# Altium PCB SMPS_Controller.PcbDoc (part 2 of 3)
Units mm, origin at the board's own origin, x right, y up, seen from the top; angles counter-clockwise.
Board outline 157 x 106 mm, 2 copper layers (Top Layer, Bottom Layer); 245 components, 175 nets, 948 pads, 171 vias.
Unrouted connection lines stored in the file: 2.
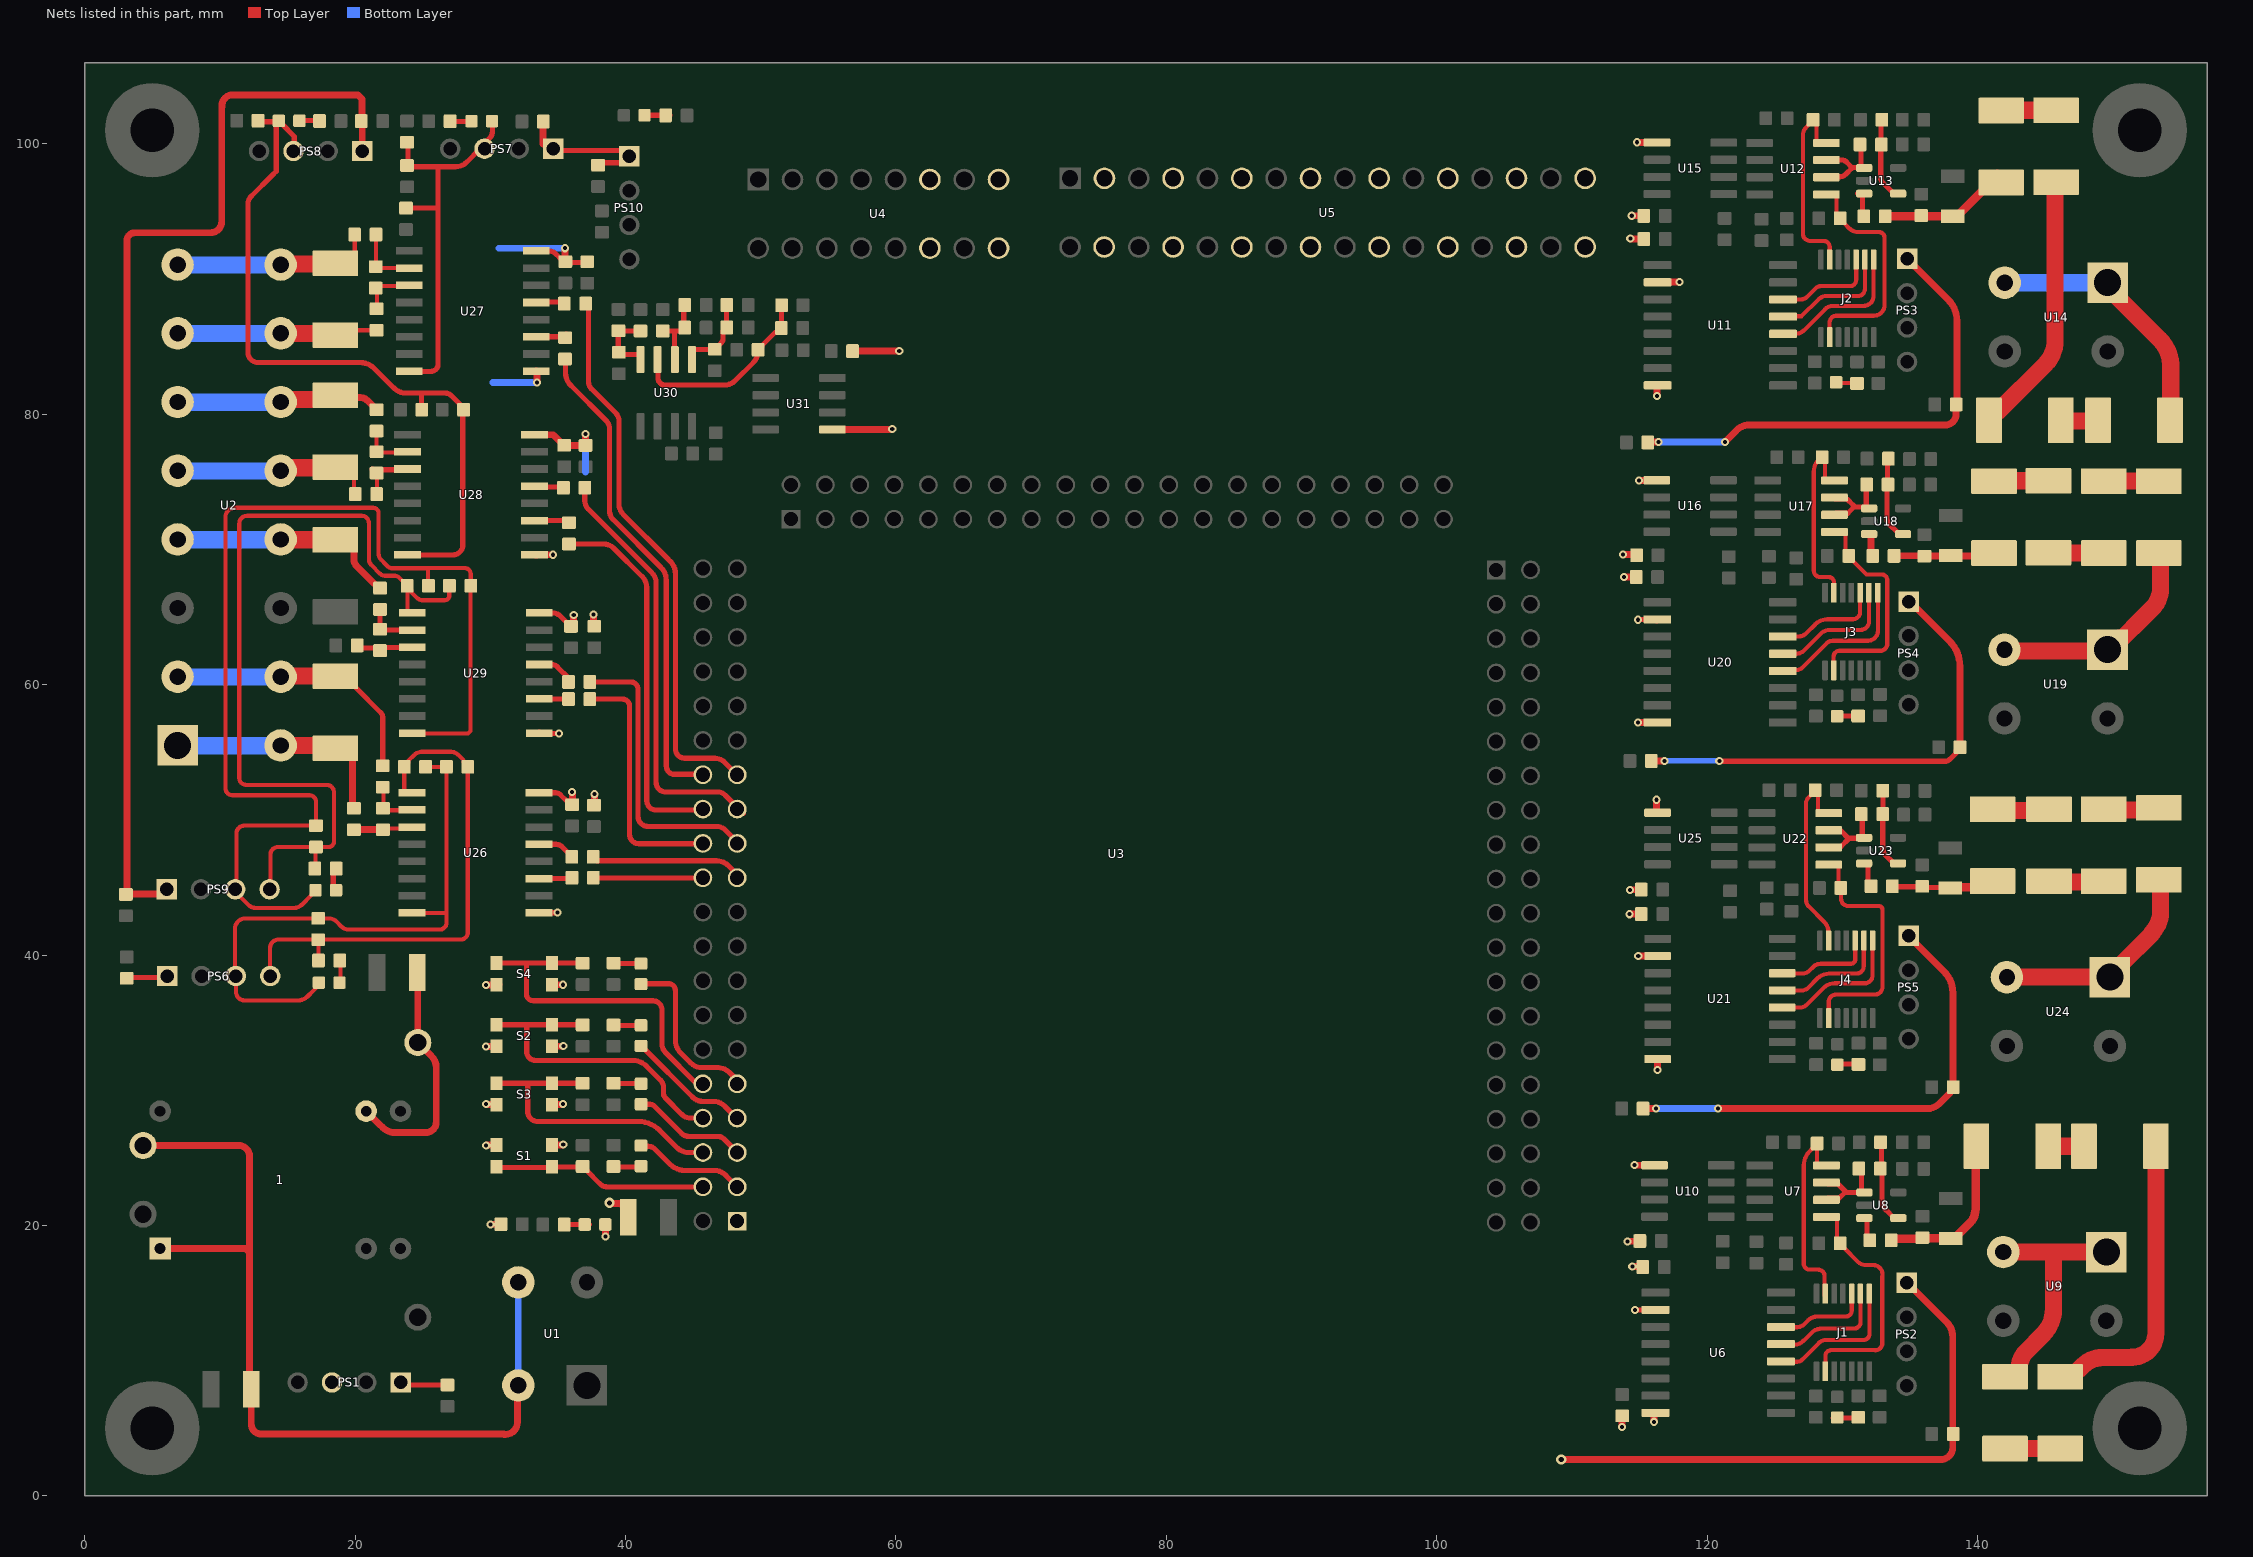
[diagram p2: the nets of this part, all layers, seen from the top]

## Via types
v1: diameter 0.6, hole 0.3, Top Layer to Bottom Layer, tented both sides, 163 vias
v2: diameter 0.762, hole 0.381, Top Layer to Bottom Layer, tented both sides, 8 vias

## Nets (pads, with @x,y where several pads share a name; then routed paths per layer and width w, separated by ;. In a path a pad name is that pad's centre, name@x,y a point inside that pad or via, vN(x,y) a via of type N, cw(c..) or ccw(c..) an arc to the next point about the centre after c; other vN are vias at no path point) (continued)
5V0_ISO3: C82.1 C83.1 C88.2 PS9.4 R69.2 U29.1 | length 62.7
  Top Layer w0.305: 11.43,53.087 ccw(c11.93,53.087) 11.951,52.588 cw(c11.962,52.283) 11.962,52.588 17.877,52.588 cw(c17.877,52.023) 18.441,52.023 ; 11.43,53.089 11.43,71.897 cw(c12.022,71.897) 12.022,72.488 20.488,72.488 cw(c20.488,71.956) 21.02,71.956 21.02,69.286 ccw(c21.629,69.286) 21.198,68.855 ; PS9.4@13.678,44.856 13.735,44.913 13.735,47.417 cw(c14.302,47.417) 14.302,47.984 C88.2@17.098,47.984 ; R69.2@17.062,46.272 C88.2@17.062,47.948 ; C88.2@17.102,47.988 18.034,47.988 ccw(c18.034,48.393) 18.438,48.393 18.438,52.023 ; 21.197,68.854 21.856,68.196 ; 21.857,68.197 ccw(c22.208,68.548) 22.208,68.052 22.947,68.052 cw(c22.947,67.627) 23.247,67.927 ; 23.246,67.926 23.504,67.668 23.772,67.668 C83.1@23.876,67.564 ; C83.1@23.848,67.31 23.848,67.133 23.985,67.133 24.166,66.952 24.166,66.815 24.535,66.446 ccw(c25.06,66.971) 25.06,66.229 ; C83.1@23.876,67.082 23.876,65.532 24.003,65.405 U29.1@24.257,65.405 ; 25.06,66.237 26.622,66.237 ; 26.622,66.24 ccw(c26.622,66.584) 26.965,66.584 C82.1@26.965,67.297
5V0_ISO4: C61.1 C62.1 C67.2 PS6.4 R51.2 U26.1 | length 39.1
  Top Layer w0.305: PS6.4@13.716,38.1 13.716,40.52 cw(c14.338,40.52) 14.338,41.142 C67.2@17.265,41.142 ; R51.2@17.244,39.37 17.3,39.426 C67.2@17.3,40.952 ; C67.2@17.428,40.943 17.628,41.143 27.802,41.143 ccw(c27.802,41.675) 28.334,41.675 C61.1@28.334,53.92 ; U26.1@23.622,52.07 23.632,52.08 C62.1@23.632,53.917 23.949,54.235 23.949,54.374 24.376,54.8 ; 24.374,54.802 cw(c24.925,54.251) 24.925,55.03 27.093,55.03 cw(c27.093,54.314) 27.599,54.82 ; 27.602,54.823 28.017,54.409 28.017,54.278 28.187,54.108 C61.1@28.442,54.108
AGND_ISO1: C68.2 C69.2 C74.1 D11.C PS7.3 U27.8 | length 29.5
  Top Layer w0.381: C69.2@23.553,95.252 26.124,95.252 ; C68.2@23.844,98.396 23.907,98.46 C74.1@23.907,100.156 ; C68.2@23.907,98.304 26.138,98.304 27.434,98.304 27.435,98.304 ccw(c27.435,99.463) 28.255,98.644 PS7.3@29.21,99.598 ; U27.8@24.017,83.171 25.614,83.171 ccw(c25.614,83.695) 26.138,83.695 26.138,95.252 26.138,98.214 ; PS7.3@29.21,99.636 29.21,99.686 29.962,100.437 ccw(c29.499,100.9) 30.153,100.9 30.153,101.409 D11.C@30.128,101.684
AGND_ISO2: C75.2 C76.2 C81.1 D12.C PS8.3 U28.8 | length 55
  Top Layer w0.381: 12.075,84.582 12.075,95.553 cw(c12.893,95.553) 12.315,96.131 ; 12.079,84.582 12.079,84.562 ccw(c12.82,84.562) 12.82,83.82 14.272,83.82 20.377,83.82 cw(c20.377,82.361) 21.41,83.392 21.411,83.39 22.889,81.912 ; 12.325,96.121 13.89,97.686 14.173,97.968 14.173,101.518 D12.C@14.358,101.704 ; C81.1@12.751,101.636 D12.C@14.202,101.636 ; D12.C@14.358,101.686 14.366,101.686 14.622,101.429 14.622,101.421 15.494,100.549 PS8.3@15.494,100.076 ; 22.892,81.916 ccw(c23.747,82.77) 23.747,81.562 24.92,81.562 26.694,81.562 cw(c26.694,80.996) 27.094,81.396 27.743,80.747 27.743,80.656 C75.2@28.022,80.337 ; U28.8@23.876,69.596 27.231,69.596 ccw(c27.231,70.333) 27.968,70.333 C75.2@27.968,80.264 ; C76.2@24.92,80.264 24.92,81.493
AGND_ISO3: C82.2 C83.2 C88.1 D13.C PS9.3 U29.8 | length 86
  Top Layer w0.305: PS9.3@11.138,44.856 11.214,44.932 11.214,48.965 cw(c11.817,48.965) 11.817,49.568 C88.1@17.102,49.568 17.102,51.346 ccw(c16.632,51.346) 16.632,51.816 10.922,51.816 cw(c10.922,52.324) 10.414,52.324 10.414,72.4 cw(c11.093,72.4) 11.093,73.079 21.336,73.079 cw(c21.336,72.677) 21.738,72.677 21.738,69.701 ccw(c22.438,69.701) 21.943,69.206 ; PS9.3@11.143,44.674 12.116,43.702 ; 12.117,43.703 ccw(c12.649,44.235) 12.649,43.483 15.507,43.483 ccw(c15.507,44.183) 16.002,43.688 ; 16.017,43.673 16.773,44.429 16.773,44.489 D13.C@17.075,44.791 ; 21.945,69.208 22.268,68.885 22.402,68.75 ; 22.406,68.754 ccw(c22.766,69.114) 22.766,68.605 25.4,68.605 ; U29.8@24.221,56.409 24.249,56.381 28.353,56.381 28.531,56.56 28.531,67.283 28.554,67.67 28.554,68.173 ccw(c28.109,68.173) 28.109,68.618 25.4,68.618 ; 25.4,68.513 25.4,67.668 C83.2@25.504,67.564
AGND_ISO4: C61.2 C62.2 C67.1 D10.C PS6.3 U26.8 | length 44.2
  Top Layer w0.305: 16.454,36.917 cw(c15.795,37.576) 15.795,36.643 11.819,36.643 cw(c11.819,37.276) 11.186,37.276 11.186,38.09 11.118,38.158 11.118,41.946 cw(c11.874,41.946) 11.874,42.702 C67.1@17.255,42.702 ; 16.459,36.912 16.91,37.363 16.91,37.369 17.207,37.666 D10.C@17.212,37.666 ; C67.1@17.27,42.717 17.288,42.7 18.07,42.7 cw(c18.07,41.917) 18.623,42.47 ; 18.622,42.469 19.011,42.079 ; 19.015,42.083 ccw(c19.501,42.568) 19.501,41.882 26.262,41.882 ccw(c26.262,42.374) 26.754,42.374 26.754,43.112 26.754,53.562 C61.2@26.754,53.92 ; U26.8@24.207,43.112 26.674,43.112 26.728,43.166 ; C62.2@25.212,53.917 26.347,53.917 C61.2@26.702,53.562 ; C61.2@26.347,53.919 C61.2@26.754,53.92
GND_3V3: 1.10 1.500 C1.2 C2.2 C4.1 C5.2 C15.2 C17.1 C19.2 C29.1 C31.2 C33.2 C43.2 C45.1 C47.2 C57.1 C59.2 C63.2 C64.2 C66.1 C70.2 C71.2 C73.1 C77.2 C78.2 C80.1 C84.2 C85.2 C87.1 C95.2 C97.1 C99.1 C100.2 C101.2 C102.2 C103.2 D1.C PS1.1 PS1.3 PS2.1 PS3.1 PS4.1 PS5.1 PS6.1 PS7.1 PS8.1 PS9.1 PS10.1 S1.1 S1.3 S2.1 S2.3 S3.1 S3.3 S4.1 S4.3 U3.A01 U4.6 U4.8 U5.2 U5.4 U5.6 U5.8 U5.10 U5.12 U5.14 U5.16 U6.2 U6.8 U10.5 U11.2 U11.8 U15.5 U16.5 U20.2 U20.8 U21.2 U21.8 U25.5 U26.9 U26.16 U27.9 U27.16 U28.9 U28.16 U29.9 U29.16 U31.5 | length 345.6
  Top Layer w0.381: C66.1@3.107,38.275 3.171,38.339 5.851,38.339 PS6.1@6.072,38.559 ; PS1.1@23.368,8.382 23.561,8.189 26.383,8.189 C1.2@26.416,8.156 ; U28.9@33.274,69.596 33.363,69.507 U28.9@33.458,69.507 ; U27.16@33.401,92.075 34.354,92.075 cw(c34.354,91.435) 34.807,91.887 ; U26.9@33.605,43.112 33.623,43.129 34.945,43.129 v1(34.963,43.147) ; U26.16@33.605,52.002 34.828,52.002 cw(c34.828,51.518) 35.17,51.86 ; U29.16@33.619,65.299 34.601,65.299 cw(c34.601,64.45) 35.201,65.051 ; U29.9@33.64,56.388 33.643,56.39 35.068,56.39 v1(35.087,56.371) ; PS7.1@33.906,99.994 PS7.1@34.263,99.636 ; PS7.1@34.29,99.636 34.408,99.518 39.785,99.518 PS10.1@40.23,99.074 ; 34.811,91.891 35.134,91.568 35.273,91.568 C70.2@35.553,91.288 ; 35.171,51.861 35.63,51.403 35.772,51.403 C63.2@36.051,51.123 ; 35.199,65.049 35.657,64.591 35.657,64.466 35.736,64.386 C84.2@35.862,64.386 ; C70.2@35.754,91.234 C71.2@37.171,91.234 ; C71.2@37.171,91.278 37.263,91.186 C71.2@37.472,91.186 ; C97.1@37.853,98.298 C97.1@37.974,98.419 ; C97.1@38.088,98.436 38.256,98.605 39.666,98.605 39.824,98.763 PS10.1@39.824,99.241 ; v1(114.273,43.018) v1@114.276,43.021 ; v1(114.313,44.815) v1@114.325,44.826 ; v1(114.675,13.73) 114.689,13.743 116.171,13.743 U6.2@116.184,13.757 ; v1(114.901,64.797) 114.915,64.811 116.241,64.811 U20.2@116.274,64.778 ; C59.2@115.127,44.826 C59.2@115.138,44.837 ; C47.2@115.136,43.021 C47.2@115.138,43.023 ; v1@120.93,54.33 137.598,54.33 ccw(c137.598,54.85) 137.966,54.482 138.43,54.946 C45.1@138.43,55.118
  Top Layer w0.508: C87.1@3.046,44.482 3.122,44.558 3.122,92.839 cw(c3.702,92.839) 3.702,93.419 9.306,93.419 ccw(c9.306,94.251) 10.138,94.251 10.138,102.732 ; C87.1@3.097,44.506 5.892,44.506 PS9.1@6.063,44.678 ; 10.148,102.732 10.148,102.83 cw(c10.927,102.83) 10.927,103.609 20.206,103.609 20.503,103.311 20.503,101.729 C80.1@20.458,101.684 20.533,101.608 PS8.1@20.533,99.481 ; 1.10@20.818,28.448 21.839,27.427 ; 21.844,27.432 22.016,27.26 ; 22.016,27.26 ccw(c22.953,28.197) 22.953,26.872 23.196,26.872 25.235,26.872 ccw(c25.235,27.636) 25.999,27.636 25.999,31.68 ccw(c24.822,31.68) 25.654,32.512 1.500@24.638,33.528 C4.1@24.638,39.37 ; v1(29.669,37.782) 29.682,37.795 30.627,37.795 S4.1@30.651,37.819 ; v1(29.671,33.243) 29.674,33.24 30.458,33.24 S2.1@30.462,33.236 ; v1(29.697,28.965) 29.714,28.947 30.433,28.947 S3.1@30.462,28.918 ; v1(29.697,25.922) 29.709,25.934 S1.3@30.48,25.934 ; v1(30.006,20.074) 30.014,20.083 30.781,20.083 C2.2@30.789,20.091 ; U28.16@33.274,78.486 33.283,78.477 34.659,78.477 35.208,77.927 35.208,77.92 35.424,77.704 C77.2@35.432,77.704 ; U27.9@33.401,83.185 33.422,83.185 33.448,83.16 v1(33.448,82.344) ; U28.9@33.553,69.602 34.64,69.602 v1(34.646,69.607) ; U29.9@33.619,56.409 U29.9@33.64,56.388 ; PS7.1@33.906,99.994 C73.1@33.906,101.865 ; S1.1@34.562,25.946 34.574,25.958 35.385,25.958 v1(35.397,25.97) ; S3.3@34.562,28.918 34.598,28.954 35.369,28.954 v1(35.387,28.972) ; S2.3@34.562,33.236 34.579,33.253 35.382,33.253 v1(35.398,33.269) ; S4.3@34.562,37.808 34.567,37.803 35.377,37.803 v1(35.381,37.799) ; C77.2@35.507,77.661 C77.2@35.464,77.704 35.47,77.698 36.804,77.698 C78.2@36.83,77.724 ; v1(35.519,92.28) 35.536,92.263 35.536,91.305 C70.2@35.553,91.288 ; C84.2@35.97,64.306 35.97,64.335 36.157,64.522 36.157,65.133 v1(36.174,65.151) ; v1(36.048,52.06) 36.048,52.035 36.079,52.005 36.079,51.151 C63.2@36.051,51.123 ; C78.2@37.047,77.694 v1@37.047,78.536 ; v1(37.625,65.183) 37.642,65.165 37.642,64.362 C85.2@37.688,64.317 ; C64.2@37.667,51.081 37.704,51.117 37.704,51.877 v1(37.721,51.894) ; D1.C@38.507,20.067 38.52,20.055 38.52,19.202 v1(38.532,19.189) ; v2(38.821,21.665) 38.87,21.616 39.651,21.616 39.786,21.482 C99.1@40.203,20.6 ; U31.5@55.302,78.867 59.524,78.867 59.54,78.883 59.712,78.883 v1(59.73,78.901) ; C95.2@56.739,84.658 56.747,84.667 v1(60.251,84.667) ; v2(109.22,2.681) 137.283,2.681 ccw(c137.283,3.574) 138.176,3.574 138.176,4.544 C17.1@138.204,4.572 ; v1(113.72,5.094) 113.721,5.096 113.721,5.908 C103.2@113.723,5.91 ; v1(113.795,69.632) 113.813,69.614 114.749,69.614 C33.2@114.789,69.575 ; v1(113.846,67.969) 113.852,67.963 114.751,67.963 C43.2@114.757,67.957 ; v1(114.122,18.811) 114.14,18.828 115.014,18.828 C15.2@115.032,18.846 ; v1@114.276,43.021 C47.2@115.136,43.021 ; v1(114.32,92.988) 114.334,92.974 115.311,92.974 C31.2@115.325,92.96 ; v1@114.325,44.826 C59.2@115.127,44.826 ; v1(114.43,94.68) 114.434,94.675 115.316,94.675 C19.2@115.32,94.671 ; v1(114.47,16.972) 114.488,16.954 115.22,16.954 C5.2@115.248,16.926 ; v1(114.639,24.455) 114.642,24.452 116.107,24.452 U10.5@116.11,24.449 ; v1(114.806,100.116) 114.818,100.105 116.285,100.105 U15.5@116.296,100.093 ; v1(114.881,57.189) 114.889,57.197 116.312,57.197 U20.8@116.32,57.204 ; v1(114.911,39.934) 114.917,39.928 116.34,39.928 U21.2@116.345,39.923 ; v1(114.952,75.098) 114.962,75.107 116.27,75.107 U16.5@116.279,75.116 ; C100.2@115.266,28.643 v1(116.229,28.643) ; C102.2@115.619,77.916 115.635,77.932 116.397,77.932 v1(116.413,77.948) ; C101.2@115.876,54.356 v1(116.84,54.356) ; v1(116.064,5.473) 116.064,6.091 116.138,6.091 U6.8@116.184,6.137 ; v1(116.263,51.483) 116.263,50.57 116.309,50.524 U25.5@116.338,50.524 ; U20.2@116.274,64.778 U20.2@116.32,64.824 ; v1(116.288,81.36) 116.288,82.093 116.296,82.093 U11.8@116.342,82.139 ; v1(116.332,31.496) 116.332,32.289 U21.8@116.345,32.303 ; U11.2@116.342,89.759 116.353,89.77 117.953,89.77 v1(117.964,89.781) ; v1(120.801,28.643) 136.318,28.643 ccw(c136.318,29.839) 137.163,28.993 ; v1(121.316,77.957) 122.162,78.803 cw(c123.126,77.84) 123.126,79.203 137.621,79.203 ccw(c137.621,80.005) 138.423,80.005 C29.1@138.423,80.719 ; PS2.1@134.814,15.757 137.708,12.863 cw(c136.579,11.734) 138.176,11.734 C17.1@138.176,4.572 ; PS3.1@134.823,91.492 134.823,91.463 135.357,90.929 135.387,90.929 137.821,88.494 137.823,88.492 cw(c136.221,86.89) 138.487,86.891 138.487,86.888 138.487,80.719 C29.1@138.463,80.719 ; PS4.1@134.874,66.294 137.925,63.243 ; PS5.1@134.918,41.416 135.418,40.916 135.418,40.895 137.525,38.788 cw(c135.954,37.213) 138.179,37.213 C57.1@138.179,30.251 ; 137.161,28.996 137.988,29.823 137.988,30.01 C57.1@138.204,30.226 ; 137.921,63.24 cw(c136.044,61.362) 138.699,61.362 C45.1@138.699,55.84
  Bottom Layer w0.381: v1@116.867,54.368 v1@120.892,54.368
  Bottom Layer w0.508: 30.178,82.344 v1(33.448,82.344) ; 30.656,92.28 v1(35.519,92.28) ; 37.046,75.73 v1(37.046,78.537) ; v1@116.214,28.643 v1(120.801,28.643) ; v1(116.413,77.948) 116.418,77.952 121.311,77.952 v1(121.316,77.957)
  other v1: 120.904,54.356
Net1_1: 1.1 1.100 C3.1 U1.2 | length 65.7
  Top Layer w0.508: 1.100@4.318,25.908 11.394,25.908 cw(c11.394,25.11) 12.192,25.11 12.192,17.99 ; 1.1@5.578,18.288 11.894,18.288 12.192,17.99 ; C3.1@12.192,8.754 12.192,17.99 ; C3.1@12.317,7.882 12.317,5.31 ccw(c13.069,5.31) 13.069,4.558 31.02,4.558 ; 31.02,4.544 31.129,4.544 ccw(c31.129,5.42) 32.004,5.42 U1.2@32.004,8.682
  Bottom Layer w0.508: U1.2@32.07,8.168 32.07,15.052 U1.2@32.766,15.748
NetC12_1: C12.1 R11.1 R12.2 R14.2 | length 12.2
  Top Layer w0.635: R12.2@133.62,18.898 133.731,19.01 135.848,19.01 C12.1@135.932,19.094 ; C12.1@135.97,19.056 R14.2@137.927,19.056 ; R14.2@137.954,19.028 138.334,19.028 138.497,19.191 138.502,19.259 139.446,20.203 ; 139.45,20.2 ccw(c138.453,21.197) 139.863,21.197 139.863,25.716 R11.1@139.726,25.853
NetC13_2: C13.2 J1.9 U7.1 | length 17.7
  Top Layer w0.305: J1.9@128.746,9.264 128.746,10.332 cw(c129.184,10.332) 129.184,10.77 132.449,10.77 ; U7.1@128.83,20.624 129.452,20.624 129.6,20.477 129.6,18.925 C13.2@129.846,18.679 ; C13.2@129.936,18.536 129.949,18.536 130.164,18.321 130.164,18.308 131.171,17.301 ccw(c131.757,17.887) 131.757,17.058 132.308,17.058 cw(c132.308,16.402) 132.964,16.402 132.964,16.225 ; 132.449,10.767 ccw(c132.449,11.279) 132.961,11.279 132.961,16.225
NetC14_1: C14.1 J1.6 U7.4 | length 14.5
  Top Layer w0.305: 127.149,24.429 127.149,17.172 ccw(c127.594,17.172) 127.594,16.727 128.219,16.727 cw(c128.219,16.252) 128.694,16.252 J1.6@128.694,14.827 ; 127.149,24.431 cw(c128.626,24.431) 127.581,25.475 127.813,25.707 127.821,25.707 C14.1@127.939,25.825 ; C14.1@128.044,25.825 128.139,25.73 128.139,24.582 128.286,24.434 U7.4@128.83,24.434
NetC26_1: C26.1 R20.1 R21.2 R23.2 | length 9.7
  Top Layer w0.635: R21.2@133.178,94.647 C26.1@135.801,94.647 ; C26.1@135.761,94.639 138.031,94.639 R23.2@138.077,94.685 ; R23.2@138.14,94.685 138.52,94.685 141.478,97.642 R20.1@141.478,97.79
NetC27_1: C27.1 J2.6 U12.4 | length 14.6
  Top Layer w0.305: 127.084,100.608 127.084,93.374 ccw(c127.646,93.374) 127.646,92.812 128.62,92.812 cw(c128.62,92.361) 129.07,92.361 J2.6@129.07,91.438 ; 127.084,100.609 cw(c127.984,100.609) 127.348,101.245 127.52,101.417 C27.1@127.837,101.775 128.106,101.507 128.106,100.215 128.253,100.068 U12.4@128.826,100.068
NetC28_1: C28.1 J2.9 U12.1 | length 16.7
  Top Layer w0.305: J2.9@129.067,85.701 129.067,86.801 cw(c129.545,86.801) 129.545,87.28 132.333,87.28 ccw(c132.333,88.077) 133.13,88.077 133.13,93.056 ccw(c132.714,93.056) 132.714,93.472 131.169,93.472 cw(c131.169,94.339) 130.556,93.726 ; U12.1@129.552,96.216 129.582,96.187 129.582,94.75 130.121,94.21 130.121,94.149 130.55,93.72
NetC40_1: C40.1 R29.1 R30.2 R32.2 | length 7.5
  Top Layer w0.381: R30.2@133.83,69.523 R30.2@133.877,69.476
  Top Layer w0.508: R30.2@133.839,69.533 C40.1@136.045,69.533 ; C40.1@136.089,69.516 R32.2@138.001,69.516 ; R32.2@138.053,69.506 140.912,69.506 R29.1@141.214,69.809
NetC41_2: C41.2 J3.6 U17.4 | length 12.9
  Top Layer w0.305: J3.6@129.35,66.823 J3.6@129.375,66.797 ; 129.384,67.555 ccw(c128.978,67.555) 128.978,67.961 128.358,67.961 cw(c128.358,68.429) 127.89,68.429 127.89,75.739 127.89,75.749 cw(c129.138,75.749) 128.164,76.529 128.177,76.542 128.197,76.561 128.562,76.631 128.724,76.469 128.724,75.099 128.772,75.052 U17.4@129.398,75.052
NetC42_2: C42.2 J3.9 U17.1 | length 15.9
  Top Layer w0.305: J3.9@129.363,61.069 129.363,62.078 cw(c129.786,62.078) 129.786,62.501 132.808,62.501 ccw(c132.808,63.024) 133.331,63.024 133.331,67.725 ccw(c132.907,67.725) 132.907,68.149 131.796,68.149 130.791,69.154 130.791,69.206 130.228,69.769 130.228,71.143 130.165,71.206 U17.1@129.961,71.206
NetC54_1: C54.1 R38.1 R39.2 R41.2 | length 7.5
  Top Layer w0.381: R39.2@133.824,44.767 R39.2@133.824,44.998 ; R39.2@133.824,44.961 133.912,45.049 135.881,45.049 C54.1@135.915,45.083 ; C54.1@135.881,45.001 137.34,45.001 R41.2@137.451,44.89
  Top Layer w0.635: R41.2@137.989,44.968 138.046,45.025 140.775,45.025 R38.1@141.149,45.399 ; R38.1@140.296,45.8 R38.1@140.296,46.012
NetC55_1: C55.1 J4.6 U22.4 | length 13.2
  Top Layer w0.305: 127.325,44.063 ccw(c127.998,44.063) 127.522,43.587 127.523,43.586 128.668,42.442 cw(c127.916,41.69) J4.6@128.979,41.69 ; 127.325,44.064 127.325,51.26 cw(c127.823,51.26) 127.471,51.612 ; 127.465,51.618 C55.1@127.996,52.149 ; C55.1@127.996,52.189 C55.1@127.996,52.149 ; U22.4@128.384,50.536 128.278,50.536 128.207,50.607 128.207,51.939 C55.1@127.996,52.149
NetC56_1: C56.1 J4.9 U22.1 | length 17.7
  Top Layer w0.305: J4.9@128.996,35.332 128.996,36.538 cw(c129.526,36.538) 129.526,37.068 132.397,37.068 ccw(c132.397,37.646) 132.975,37.646 132.975,43.336 ccw(c132.68,43.336) 132.68,43.631 130.474,43.631 ; U22.1@129.687,46.687 129.734,46.64 129.734,45.122 C56.1@129.895,44.961 ; C56.1@129.817,44.922 129.919,44.821 129.919,44.139 ccw(c130.428,44.139) 130.428,43.629 130.474,43.629
NetC65_1: C65.1 R50.2 U26.3 | length 3.2
  Top Layer w0.305: C65.1@22.326,49.25 C65.1@22.352,49.276 ; C65.1@22.352,49.365 23.457,49.365 U26.3@23.622,49.53
  Top Layer w0.508: R50.2@20.208,49.276 C65.1@22.076,49.276
NetC65_2: C65.2 R46.2 U26.2 | length 3.8
  Top Layer w0.305: R46.2@21.953,52.198 R46.2@21.981,52.227 ; C65.2@22.058,50.977 22.058,51.108 22.058,50.833 22.058,50.604 C65.2@22.095,50.567 ; C65.2@22.098,50.833 22.098,51.108 R46.2@22.098,52.014 ; C65.2@22.235,50.703 22.612,50.703 24.033,50.703 U26.2@24.13,50.8
NetC72_1: C72.1 R56.2 U27.3 | length 3.1
  Top Layer w0.305: R56.2@21.659,87.829 21.625,87.863 21.625,89.275 21.843,89.492 U27.3@23.174,89.492
NetC72_2: C72.2 R52.2 U27.2 | length 4.7
  Top Layer w0.305: C72.2@21.526,90.912 21.533,90.919 R52.2@21.533,93.275 ; C72.2@21.659,90.888 21.746,90.801 U27.2@23.999,90.801
NetC79_1: C79.1 R62.2 U28.3 | length 4.5
  Top Layer w0.305: R62.2@21.611,74.111 C79.1@21.611,75.626
  Top Layer w0.381: C79.1@21.27,75.926 21.55,75.647 C79.1@21.59,75.647 ; C79.1@21.463,75.774 C79.1@21.59,75.647 ; U28.3@23.876,75.946 23.82,75.89 21.833,75.89 21.74,75.796 C79.1@21.59,75.647
NetC79_2: C79.2 R58.2 U28.2 | length 3.3
  Top Layer w0.305: R58.2@21.59,78.698 21.59,77.576 21.71,77.456 C79.2@21.844,77.456 ; C79.2@22.098,77.17 U28.2@23.928,77.17
NetC86_1: C86.1 R68.2 U29.3 | length 4.3
  Top Layer w0.381: R68.2@20.153,62.898 20.341,62.71 21.651,62.71 C86.1@21.844,62.517 22.066,62.739 U29.3@24.2,62.739
NetC86_2: C86.2 R64.2 U29.2 | length 3.6
  Top Layer w0.381: C86.2@21.844,64.097 21.913,64.028 U29.2@24.219,64.028 ; C86.2@21.844,64.229 R64.2@21.844,65.415
NetC91_2: C91.2 R70.2 R72.1 U30.1 | length 5.8
  Top Layer w0.381: U30.1@44.958,84.074 44.958,84.684 45.067,84.794 C91.2@46.606,84.794 ; C91.2@46.646,84.8 C91.2@46.606,84.8 47.078,85.273 ccw(c46.739,85.612) 47.219,85.612 47.218,86.137 R72.1@47.498,86.417 ; R72.1@47.47,86.417 R70.2@47.47,87.884
NetC92_2: C92.2 R71.2 R73.1 U30.3 | length 14.6
  Top Layer w0.381: U30.3@42.379,84.046 42.406,83.252 42.406,82.669 ccw(c42.917,82.669) 42.917,82.157 47.326,82.157 47.328,82.157 ccw(c47.328,83.27) 48.115,82.483 49.48,83.849 ccw(c48.748,84.582) C92.2@49.784,84.582 ; C92.2@49.796,84.722 50.075,85.002 50.075,85.057 51.075,86.057 51.251,86.057 51.308,86.114 R73.1@51.308,86.614 ; R73.1@51.534,86.36 R71.2@51.534,88.138
NetC93_1: C93.1 R74.2 R75.1 U30.2 | length 5.5
  Top Layer w0.381: R74.2@42.758,86.158 43.622,86.158 ; U30.2@43.649,84.046 43.622,84.073 43.622,86.158 ; R75.1@44.38,86.406 44.312,86.474 44.312,88 C93.1@44.389,88.077 ; R75.1@44.398,86.158 43.622,86.158
NetC94_1: C94.1 R76.2 R77.1 U30.4 | length 5.1
  Top Layer w0.381: C94.1@39.509,84.58 39.468,84.621 39.468,86.014 39.6,86.146 41.08,86.146 R76.2@41.119,86.107 ; C94.1@39.538,84.519 39.629,84.428 41.039,84.428 41.148,84.318 U30.4@41.148,84.074
NetD1_A: D1.A R1.1 | length 1.6
  Top Layer w0.305: R1.1@35.469,20.059 R1.1@35.491,20.081
  Top Layer w0.381: R1.1@35.792,20.078 D1.A@37.328,20.078
NetD2_A: D2.A R2.1 | length 1.8
  Top Layer w0.381: R2.1@39.358,24.318 41.08,24.318 D2.A@41.148,24.386
NetD2_C: D2.C U3.A03 | length 8.4
  Top Layer w0.381: D2.C@41.17,25.928 41.241,25.856 41.675,25.856 cw(c41.675,25.165) 42.164,25.654 43.298,24.52 43.299,24.519 ccw(c44.385,25.604) 44.385,24.069 44.386,24.069 46.551,24.069 cw(c46.551,22.834) 47.425,23.707 ; 47.419,23.701 U3.A03@48.369,22.751
NetD3_A: D3.A R5.1 | length 1.8
  Top Layer w0.381: R5.1@39.116,30.508 39.131,30.493 40.881,30.493 D3.A@40.894,30.48
NetD3_C: D3.C U3.A05 | length 8.8
  Top Layer w0.381: D3.C@41.148,28.958 41.423,28.958 41.801,28.958 cw(c41.801,28.498) 42.126,28.823 44.134,26.815 ; 44.135,26.814 ccw(c44.684,27.365) 44.684,26.587 46.833,26.587 cw(c46.834,26.01) 47.242,26.418 U3.A05@48.376,25.284 ; U3.A05@48.376,25.282 U3.A05@48.463,25.197
NetD4_A: D4.A R8.1 | length 2
  Top Layer w0.381: R8.1@39.116,34.826 39.165,34.777 D4.A@41.129,34.777
NetD4_C: D4.C U3.A07 | length 9.2
  Top Layer w0.381: D4.C@41.179,33.276 41.179,33.255 41.423,33.011 41.444,33.011 44.972,29.483 44.973,29.482 ccw(c45.729,30.237) 45.729,29.169 45.73,29.169 46.516,29.169 cw(c46.516,28.021) 47.328,28.833 ; 47.324,28.828 48.218,27.934 U3.A07@48.264,27.934
NetD5_A: D5.A R9.1 | length 2.3
  Top Layer w0.381: R9.1@39.117,39.368 D5.A@41.402,39.368
NetD5_C: D5.C U3.A09 | length 12.5
  Top Layer w0.381: D5.C@41.402,37.848 41.432,37.878 43.189,37.878 cw(c43.189,37.376) 43.691,37.376 43.691,33.686 43.691,33.684 ccw(c44.982,33.684) 44.07,32.77 44.817,32.023 44.818,32.022 ccw(c45.675,32.879) 45.675,31.667 45.677,31.667 46.862,31.667 46.864,31.667 cw(c46.864,30.55) 47.654,31.34 48.479,30.515 48.479,30.51 U3.A09@48.483,30.511
NetD6_A: D6.A R18.1 | length 1.6
  Top Layer w0.381: D6.A@129.332,5.741 R18.1@130.894,5.741 ; D6.A@129.447,5.793 D6.A@129.499,5.741
NetD7_A: D7.A R27.1 | length 1.6
  Top Layer w0.305: D7.A@129.54,82.362 129.582,82.32 131.04,82.32 R27.1@131.064,82.296
NetD8_A: D8.A R36.1 | length 1.5
  Top Layer w0.381: D8.A@129.425,57.672 R36.1@130.975,57.672
NetD9_A: D9.A R45.1 | length 1.7
  Top Layer w0.381: D9.A@129.412,31.981 D9.A@129.444,31.949 ; D9.A@129.424,31.933 130.993,31.933 R45.1@131.064,32.004
NetD10_A: D10.A R51.1 | length 1.9
  Top Layer w0.305: R51.1@18.856,39.345 R51.1@19.097,39.586 ; D10.A@18.903,37.867 18.918,37.882 R51.1@18.918,39.404
NetD11_A: D11.A R57.1 | length 1.6
  Top Layer w0.381: R57.1@26.808,101.624 26.838,101.654 D11.A@28.383,101.654
NetD12_A: D12.A R63.1 | length 1.4
  Top Layer w0.381: D12.A@15.614,101.733 17,101.733 R63.1@17.006,101.739
NetD13_A: D13.A R69.1 | length 1.6
  Top Layer w0.381: D13.A@18.384,44.704 18.384,46.073 18.539,46.228 R69.1@18.542,46.228
NetD14_A: D14.A R78.1 | length 1.9
  Top Layer w0.381: D14.A@41.4,102.108 R78.1@43.27,102.108
NetJ1_1: J1.1 U6.12 | length 10.4
  Top Layer w0.305: U6.12@125.464,9.947 126.342,9.916 126.642,9.916 ccw(c126.642,10.511) 127.063,10.09 128.163,11.19 128.291,11.318 cw(c128.779,10.83) 128.779,11.521 ; 128.779,11.525 131.578,11.525 ccw(c131.578,11.957) 132.009,11.957 J1.1@132.009,14.937
NetJ1_2: J1.2 U6.13 | length 8.6
  Top Layer w0.305: U6.13@125.464,11.217 125.487,11.194 126.538,11.194 ccw(c126.538,11.925) 127.055,11.408 127.118,11.471 ; 127.129,11.46 127.712,12.043 cw(c128.507,11.249) 128.507,12.372 130.866,12.372 ccw(c130.866,12.866) 131.359,12.866 J1.2@131.359,14.839
NetJ1_3: J1.3 U6.14 | length 7
  Top Layer w0.305: U6.14@125.483,12.467 126.664,12.467 ccw(c126.664,13.18) 127.167,12.676 ; 127.171,12.673 127.476,12.978 cw(c128.145,12.31) 128.145,13.255 130.252,13.255 ccw(c130.252,13.703) 130.699,13.703 J1.3@130.699,14.946
NetJ2_1: J2.1 U11.12 | length 10.5
  Top Layer w0.305: U11.12@125.622,85.949 126.581,85.949 ccw(c126.581,86.708) 127.117,86.171 ; 127.124,86.165 128.745,87.787 cw(c129.299,87.234) 129.299,88.016 131.578,88.016 ccw(c131.578,88.758) 132.32,88.758 J2.1@132.32,91.339
NetJ2_2: J2.2 U11.13 | length 9.6
  Top Layer w0.305: U11.13@125.141,87.25 126.993,87.25 128.241,88.497 cw(c128.845,87.894) 128.845,88.748 131.177,88.748 ccw(c131.177,89.245) 131.674,89.245 J2.2@131.674,91.435
NetJ2_3: J2.3 U11.14 | length 7.5
  Top Layer w0.305: U11.14@125.628,88.495 126.5,88.495 126.961,88.495 ccw(c126.961,89.1) 127.389,88.672 128.049,89.332 ; 128.05,89.333 cw(c128.387,88.995) 128.387,89.472 130.562,89.472 ccw(c130.562,89.944) 131.034,89.944 J2.3@131.034,91.424
NetJ3_1: J3.1 U20.12 | length 10.5
  Top Layer w0.305: U20.12@125.6,61.014 126.477,61.079 126.624,61.079 ccw(c126.624,61.648) 127.052,61.272 128.829,63.049 cw(c129.3,62.578) 128.83,63.051 cw(c129.3,62.578) 129.3,63.245 131.902,63.245 ccw(c131.902,63.974) 132.631,63.974 J3.1@132.631,66.224
NetJ3_2: J3.2 U20.13 | length 9.6
  Top Layer w0.305: U20.13@125.6,62.284 126.628,62.284 ccw(c126.628,62.995) 127.13,62.492 128.38,63.741 cw(c129.116,63.006) 129.116,64.047 131.364,64.047 ccw(c131.364,64.656) 131.973,64.656 J3.2@131.973,66.85
NetJ3_3: J3.3 U20.14 | length 7.5
  Top Layer w0.305: U20.14@125.75,63.569 126.477,63.569 126.809,63.569 ccw(c126.809,64.297) 127.325,63.783 128.005,64.463 cw(c128.901,63.568) 128.901,64.835 ; 128.902,64.835 130.783,64.835 ccw(c130.783,65.377) 131.326,65.377 J3.3@131.326,66.506
NetJ4_1: J4.1 U21.12 | length 9.4
  Top Layer w0.305: U21.12@126.32,36.121 126.857,36.121 ccw(c126.857,36.883) 127.396,36.344 ; 127.395,36.345 128.613,37.563 cw(c129.441,36.736) 129.441,37.906 131.655,37.906 ccw(c131.655,38.493) 132.242,38.493 J4.1@132.242,41.02
NetJ4_2: J4.2 U21.13 | length 8
  Top Layer w0.305: U21.13@125.567,37.371 126.985,37.371 ccw(c126.985,38.042) 127.459,37.567 ; 127.463,37.563 128.179,38.28 cw(c129.007,37.453) 129.007,38.623 131.041,38.623 ccw(c131.041,39.171) 131.59,39.171 J4.2@131.59,40.434
NetJ4_3: J4.3 U21.14 | length 7.2
  Top Layer w0.305: U21.14@125.574,38.634 127.061,38.634 ; 127.063,38.634 ccw(c127.063,39.354) 127.572,38.845 127.852,39.125 cw(c128.405,38.572) 128.405,39.355 130.644,39.355 ccw(c130.644,39.675) 130.963,39.675 130.963,40.414 130.961,40.417 J4.3@130.961,41.055
NetR3_1: R3.1 S1.2 S1.4 U3.A04 | length 15.6
  Top Layer w0.381: S1.4@30.462,24.346 30.522,24.286 34.502,24.286 S1.2@34.562,24.346 ; S1.2@34.576,24.332 R3.1@36.806,24.332 ; R3.1@36.83,24.356 36.87,24.356 37.15,24.076 37.15,24.036 38.103,23.083 ccw(c38.672,23.65) 38.672,22.847 U3.A04@45.479,22.847
NetR4_1: R4.1 S2.2 S2.4 U3.A08 | length 23.7
  Top Layer w0.381: S2.2@30.462,34.836 32.693,34.836 ; R4.1@36.576,34.902 36.51,34.836 S2.4@34.562,34.836 32.693,34.836 ; 42.809,30.189 42.809,29.748 ccw(c43.21,29.748) 42.926,29.464 ; 42.809,30.189 ccw(c41.997,30.189) 42.571,30.763 41.561,31.774 41.559,31.776 ccw(c40.527,30.744) 40.527,32.203 33.336,32.203 cw(c33.336,32.846) 32.693,32.846 32.693,34.836 ; 42.917,29.455 44.187,28.185 ; 44.196,28.194 ccw(c44.825,28.823) 44.825,27.934 U3.A08@45.724,27.934
NetR6_1: R6.1 S3.2 S3.4 U3.A06 | length 22.1
  Top Layer w0.381: S3.2@30.716,30.518 32.766,30.518 ; R6.1@36.576,30.584 36.51,30.518 S3.4@34.562,30.518 32.766,30.518 ; U3.A06@45.724,25.394 44.701,25.394 cw(c44.701,26.698) 43.777,25.777 42.516,27.038 42.515,27.039 ccw(c40.954,25.478) 40.954,27.686 40.952,27.686 33.528,27.686 cw(c33.528,28.448) 32.766,28.448 32.766,30.518
NetR7_1: R7.1 S4.2 S4.4 U3.A10 | length 26
  Top Layer w0.381: S4.2@30.716,39.408 32.668,39.408 ; S4.4@34.793,39.375 34.76,39.408 32.668,39.408 ; S4.4@34.821,39.403 R7.1@36.797,39.403 ; 42.958,32.781 45.073,30.667 45.531,30.667 U3.A10@45.724,30.474 ; 42.965,32.788 cw(c43.625,33.448) 42.691,33.448 42.691,35.912 42.691,35.913 cw(c43.072,35.912) 42.691,35.927 ccw(c42.032,35.956) 42.032,36.616 33.19,36.616 cw(c33.19,37.138) 32.668,37.138 32.668,39.408
NetR10_1: R10.1 R11.2 | length 3.2
  Top Layer w1.27: R11.2@145.24,25.853 147.56,25.853 147.927,25.486 R10.1@147.927,25.134
NetR10_2: R10.2 R13.2 | length 21.4
  Top Layer w1.27: R13.2@147.066,8.89 147.792,9.616 cw(c149.272,8.136) 149.272,10.229 151.435,10.229 ; 151.435,10.251 ccw(c151.435,12.011) 153.195,12.011 R10.2@153.195,25.853
NetR12_1: R12.1 U8.3 | length 1.9
  Top Layer w0.381: U8.3@131.637,20.54 131.726,20.54 131.831,20.435 131.831,19.107 R12.1@132.04,18.898
NetR13_1: R13.1 R15.2 | length 3.7
  Top Layer w1.27: R15.2@142.155,3.517 142.166,3.506 145.746,3.506 R13.1@145.796,3.556
NetR15_1: R15.1 U9.1 | length 16.8
  Top Layer w1.27: U9.1@141.914,18.027 144.969,18.027 145.624,18.027 ; R15.1@143.107,9.495 cw(c144.761,9.495) 143.591,10.664 144.876,11.949 ; 144.86,11.966 144.88,11.987 ccw(c143.084,13.783) 145.624,13.783 145.624,18.027 ; U9.1@149.352,18.034 149.345,18.027 145.624,18.027
NetR16_1: R16.1 U7.2 U7.3 U8.1 | length 6.3
  Top Layer w0.381: U7.2@128.83,21.894 128.94,22.004 129.768,22.004 130.254,22.49 ; U7.3@128.83,23.164 128.94,23.055 129.689,23.055 130.304,22.44 ; 130.273,22.44 131.417,22.44 U8.1@131.637,22.44 ; R16.1@131.417,23.845 131.417,22.541 U8.1@131.522,22.437
NetR16_2: R16.2 R17.1 U8.4 | length 6.1
  Top Layer w0.381: R16.2@132.759,24.112 132.944,23.927 132.944,21.735 ccw(c133.704,21.733) 133.265,21.113 133.732,20.647 133.732,20.644 U8.4@134.001,20.556 ; R16.2@132.809,24.204 132.912,24.307 132.912,26.068 R17.1@132.834,26.146
NetR19_1: R19.1 R20.2 | length 4.9
  Top Layer w1.27: R20.2@141.478,102.482 146.184,102.482 R19.1@146.304,102.362
NetR19_2: R19.2 R22.2 | length 19.4
  Top Layer w1.27: R22.2@140.85,79.894 141.165,80.209 141.541,80.209 145.001,83.669 ccw(c143.214,85.458) 145.742,85.458 R19.2@145.742,97.162
NetR21_1: R21.1 U13.3 | length 1.9
  Top Layer w0.381: U13.3@131.144,96.325 U13.3@131.248,96.221 ; R21.1@131.591,94.639 131.508,94.722 131.508,96.213 131.613,96.317 U13.3@131.62,96.317
NetR22_1: R22.1 R24.2 | length 2.7
  Top Layer w1.27: R22.1@146.174,79.498 146.179,79.502 148.9,79.502 R24.2@148.904,79.498
NetR24_1: R24.1 U14.1 | length 20.5
  Top Layer w1.27: U14.1@149.098,89.916 153.472,85.542 153.476,85.538 cw(c151.484,83.547) 154.299,83.445 ccw(c155.568,83.403) 154.298,83.405 154.298,83.403 154.298,79.622 R24.1@154.178,79.502
  Bottom Layer w0.508: U14.1@149.633,89.729 U14.1@150.008,89.729
  Bottom Layer w1.27: U14.1@142.013,89.729 U14.1@149.633,89.729
NetR25_1: R25.1 U12.2 U12.3 U13.1 | length 6.9
  Top Layer w0.381: U12.2@128.826,97.528 128.865,97.567 129.83,97.567 ccw(c129.83,98.145) 130.239,97.736 130.271,97.768 ; U12.3@128.826,98.798 129.989,98.798 cw(c129.989,98.367) 130.294,98.672 130.727,98.238 ; 130.273,97.766 130.7,98.193 ; 130.7,98.238 U13.1@131.093,98.238 ; R25.1@131.145,99.959 131.383,99.722 131.383,98.322 131.487,98.217 U13.1@131.62,98.217 ; U13.1@131.198,98.228 U13.1@131.402,98.228
NetR25_2: R25.2 R26.1 U13.4 | length 6.1
  Top Layer w0.381: R25.2@132.842,99.843 132.842,99.626 132.842,97.474 ccw(c133.295,97.474) 132.974,97.154 133.706,96.422 133.715,96.422 U13.4@134.13,96.317 ; R25.2@132.892,99.945 132.862,99.976 132.862,101.705 R26.1@132.931,101.775
NetR28_1: R28.1 R29.2 | length 4
  Top Layer w1.27: R29.2@141.285,75.128 141.329,75.084 145.165,75.084 R28.1@145.21,75.128
NetR28_2: R28.2 R31.2 | length 4
  Top Layer w1.27: R28.2@145.335,69.671 145.406,69.742 149.223,69.742 R31.2@149.293,69.671
NetR30_1: R30.1 U18.3 | length 1.7
  Top Layer w0.381: U18.3@131.986,71.135 132.012,71.135 U18.3@132.117,71.03 ; R30.1@132.117,69.743 R30.1@132.29,69.57
  Top Layer w0.508: R30.1@132.117,69.743 U18.3@132.117,71.03
NetR31_1: R31.1 R33.2 | length 4.1
  Top Layer w1.27: R31.1@149.352,75.05 R33.2@153.416,75.05
NetR33_1: R33.1 U19.1 | length 16.7
  Top Layer w1.27: U19.1@141.478,62.484 148.336,62.484 U19.1@148.844,62.992 ; U19.1@149.619,62.582 150.484,63.447 150.733,63.447 152.155,64.869 152.924,65.638 ccw(c151.424,67.138) 153.545,67.138 153.545,69.669 R33.1@153.416,69.984
NetR34_1: R34.1 U17.2 U17.3 U18.1 | length 6.2
  Top Layer w0.381: U17.3@129.409,73.793 129.481,73.721 130.35,73.721 130.809,73.262 130.946,73.125 131.896,73.125 U18.1@131.986,73.035 ; U17.2@129.423,72.561 129.533,72.67 130.41,72.67 130.891,73.152 130.932,73.152 ; R34.1@131.662,74.67 131.779,74.553 U18.1@131.779,73.162
NetR34_2: R34.2 R35.1 U18.4 | length 5.6
  Top Layer w0.381: R35.1@133.419,76.32 133.347,76.248 133.347,74.753 133.299,74.705 133.299,72.325 ccw(c133.969,72.325) 133.495,71.851 ; 133.494,71.85 134.081,71.263 134.081,71.239 134.163,71.158 U18.4@134.228,71.158
NetR37_1: R37.1 R38.2 | length 4.8
  Top Layer w1.27: R38.2@140.116,50.686 144.795,50.686 R37.1@144.821,50.713 ; R38.2@140.466,50.735 R38.2@140.493,50.708
NetR37_2: R37.2 R40.2 | length 4.2
  Top Layer w1.27: R37.2@144.904,45.4 148.967,45.4 R40.2@149.012,45.445 ; R37.2@144.992,45.41 R37.2@145.037,45.455
NetR39_1: R39.1 U23.3 | length 2.2
  Top Layer w0.381: U23.3@131.614,46.771 131.801,46.771 131.906,46.667 131.906,45.017 R39.1@132.053,44.87
NetR40_1: R40.1 R42.2 | length 4.3
  Top Layer w1.27: R40.1@149.075,50.702 149.104,50.731 153.131,50.731 R42.2@153.16,50.702 ; R40.1@149.563,50.645 R40.1@149.679,50.76
NetR42_1: R42.1 U24.1 | length 15.3
  Top Layer w1.27: U24.1@142.064,38.294 142.135,38.365 148.579,38.365 U24.1@148.59,38.354 ; U24.1@149.756,38.365 150.621,39.23 150.621,39.294 152.945,41.619 ; 152.908,41.656 ccw(c151.37,43.194) 153.545,43.194 153.545,45.248 153.416,45.377 R42.1@153.416,45.563
NetR43_1: R43.1 U22.2 U22.3 U23.1 | length 4.5
  Top Layer w0.381: U22.3@129.776,49.219 cw(c129.776,48.976) 129.948,49.148 130.469,48.627 ; U22.2@129.777,47.966 ccw(c129.777,48.116) 129.884,48.01 130.501,48.627 ; 130.458,48.638 131.581,48.638 U23.1@131.614,48.671 ; R43.1@131.358,50.093 131.477,49.974 U23.1@131.477,48.721
NetR43_2: R43.2 R44.1 U23.4 | length 5.5
  Top Layer w0.381: 132.989,49.866 132.989,47.925 ccw(c133.782,47.925) 133.222,47.364 133.71,46.876 133.814,46.771 U23.4@134.124,46.771 ; R44.1@132.992,52.157 133.025,52.124 133.025,50.451 R43.2@132.995,50.42
NetR46_1: R46.1 R49.2 U2.2 | length 18.3
  Top Layer w0.381: R49.2@20.084,59.744 21.902,57.926 cw(c21.566,57.59) 22.041,57.59 22.041,54.269 R46.1@22.041,53.99
  Top Layer w1.27: U2.2@14.478,60.452 14.664,60.638 18.608,60.638 R49.2@18.796,60.826
  Bottom Layer w1.27: U2.2@6.719,60.559 13.863,60.559 U2.2@13.97,60.452
NetR47_1: R47.1 U3.A22 | length 8.1
  Top Layer w0.381: R47.1@37.633,45.707 U3.A22@45.717,45.707
NetR47_2: R47.2 U26.11 | length 2.5
  Top Layer w0.381: U26.11@33.608,45.654 35.974,45.654 R47.2@36.04,45.72
NetR48_1: R48.1 U3.A21 | length 11.7
  Top Layer w0.381: R48.1@37.612,47.263 37.612,47.25 37.891,46.97 46.734,46.97 46.736,46.97 cw(c46.736,45.728) 47.614,46.606 48.474,45.747 48.474,45.65 U3.A21@48.613,45.608
NetR48_2: R48.2 U26.13 | length 2.8
  Top Layer w0.381: U26.13@33.605,48.192 34.858,48.192 cw(c34.858,47.558) 35.306,48.006 R48.2@36.068,47.244
NetR49_1: R49.1 R50.1 U2.1 | length 18.4
  Top Layer w0.305: R49.1@19.424,55.506 19.984,54.946 R49.1@20.066,54.864
  Top Layer w0.508: R49.1@18.542,55.299 18.796,55.299 19.111,55.299 19.277,55.299 19.807,54.769 19.807,50.952 R50.1@19.91,50.849
  Top Layer w1.27: U2.1@14.339,55.479 14.353,55.493 18.675,55.493 R49.1@18.796,55.372
  Bottom Layer w1.27: U2.1@6.719,55.479 14.117,55.479 U2.1@14.224,55.372
NetR52_1: R52.1 R55.2 U2.8 | length 15.1
  Top Layer w0.305: R55.2@18.542,91.172 19.177,91.172 19.975,91.97 19.975,93.15 19.715,93.259 19.743,93.287 R52.1@19.965,93.287
  Top Layer w1.27: U2.8@14.417,91.117 R55.2@18.487,91.117
  Bottom Layer w1.27: U2.8@6.719,91.039 14.117,91.039 U2.8@14.224,90.932
NetR53_1: R53.1 U3.A28 | length 36.1
  Top Layer w0.381: R53.1@35.532,84.084 35.569,83.805 35.569,83.053 ccw(c36.859,83.053) 35.947,82.141 35.948,82.139 38.588,79.5 cw(c38.003,78.915) 38.83,78.915 38.83,72.825 ccw(c39.712,72.825) 39.088,72.202 ; 39.09,72.204 42.633,68.661 42.634,68.66 cw(c41.71,67.735) 43.017,67.736 43.017,67.734 43.017,53.975 ccw(c43.625,53.975) 43.625,53.368 45.69,53.368 U3.A28@45.724,53.334
NetR53_2: R53.2 U27.11 | length 2.5
  Top Layer w0.381: U27.11@33.401,85.725 R53.2@35.631,85.725 ; R53.2@35.43,85.731 R53.2@35.613,85.914
NetR54_1: R54.1 U3.A27 | length 41.1
  Top Layer w0.381: R54.1@37.275,88.098 37.275,82.387 ccw(c38.019,82.387) 37.493,81.861 ; 37.497,81.865 39.26,80.102 ; 39.258,80.1 cw(c38.632,79.474) 39.518,79.474 39.518,73.38 39.518,73.378 ccw(c40.675,73.378) 39.858,72.559 43.172,69.245 43.173,69.244 ccw(c43.442,69.514) 43.201,69.219 cw(c42.362,68.18) 43.697,68.178 43.697,68.176 43.697,55.234 ccw(c44.38,55.234) 44.38,54.552 46.626,54.552 46.628,54.552 cw(c46.628,53.566) 47.396,54.183 47.41,54.169 48.364,53.216 48.373,53.216 U3.A27@48.477,53.103
NetR54_2: R54.2 U27.13 | length 1.8
  Top Layer w0.381: U27.13@33.585,88.297 R54.2@35.415,88.297
NetR55_1: R55.1 R56.1 U2.7 | length 15.6
  Top Layer w0.305: R55.1@18.542,85.852 18.903,86.213 R56.1@21.655,86.213
  Top Layer w1.27: U2.7@14.344,85.964 18.43,85.964 R55.1@18.542,85.852
  Bottom Layer w1.27: U2.7@6.719,85.959 14.585,85.959 U2.7@14.732,86.106
NetR58_1: R58.1 R61.2 U2.6 | length 14.8
  Top Layer w0.508: R61.2@18.542,81.406 18.725,81.223 20.409,81.223 cw(c20.409,80.533) 20.896,81.021 20.901,81.016 ; 20.9,81.015 21.09,80.825 21.09,80.819 R58.1@21.314,80.596
  Top Layer w1.27: U2.6@14.339,80.879 14.556,81.096 18.232,81.096 R61.2@18.542,81.406
  Bottom Layer w1.27: U2.6@6.719,80.879 13.863,80.879 U2.6@13.97,80.772
NetR59_1: R59.1 U3.A26 | length 27.6
  Top Layer w0.381: R59.1@35.814,70.399 38.408,70.399 38.41,70.399 cw(c38.409,69.405) 39.112,70.108 39.113,70.107 41.245,67.975 41.247,67.973 cw(c40.453,67.178) 41.576,67.179 41.576,67.177 41.576,51.413 ccw(c42.27,51.413) 42.27,50.72 45.65,50.72 U3.A26@45.724,50.794
NetR59_2: R59.2 U28.11 | length 2.5
  Top Layer w0.381: U28.11@33.274,72.136 35.494,72.136 35.56,72.07 R59.2@35.56,71.882
NetR60_1: R60.1 U3.A25 | length 31.4
  Top Layer w0.381: R60.1@36.99,74.566 36.99,73.587 ccw(c37.821,73.587) 37.233,73 37.239,72.994 ; 37.24,72.996 41.928,68.308 cw(c41.12,67.499) 42.264,67.499 42.264,52.777 ccw(c42.988,52.777) 42.988,52.053 46.833,52.053 cw(c46.833,51.294) 47.37,51.831 48.433,50.768 48.433,50.678 U3.A25@48.723,50.478
NetR60_2: R60.2 U28.13 | length 2.4
  Top Layer w0.381: U28.13@33.274,74.676 33.329,74.621 35.361,74.621 R60.2@35.56,74.422
NetR61_1: R61.1 R62.1 U2.5 | length 15.1
  Top Layer w0.305: R61.1@18.542,76.086 19.133,76.086 19.931,75.288 19.931,74.172 R62.1@20.011,74.092
  Top Layer w1.27: U2.5@14.339,75.799 14.556,76.016 15.355,76.016 15.379,76.041 R61.1@18.497,76.041
  Bottom Layer w1.27: U2.5@6.719,75.799 14.077,75.799 U2.5@14.478,76.2
NetR64_1: R64.1 R67.2 U2.4 | length 17.6
  Top Layer w0.305: R67.2@18.542,71.213 R67.2@19.083,71.213 ; R67.2@19.083,70.804 R67.2@19.136,70.804 ; R67.2@19.227,70.895 R67.2@19.919,70.203 ; R64.1@21.442,67.457 21.526,67.457 R64.1@21.844,67.139
  Top Layer w0.508: R67.2@19.919,70.203 19.919,70.009 19.919,69.199 ccw(c20.449,69.199) 20.077,68.822 R64.1@21.442,67.457
  Top Layer w1.27: U2.4@14.339,70.719 18.468,70.719 R67.2@18.542,70.793
  Bottom Layer w1.27: U2.4@6.719,70.719 14.117,70.719 U2.4@14.478,70.358
NetR65_1: R65.1 U3.A24 | length 18.6
  Top Layer w0.381: R65.1@37.366,58.928 39.792,58.928 cw(c39.792,58.421) 40.299,58.421 ; 40.302,58.421 40.302,48.918 ccw(c40.994,48.918) 40.994,48.226 45.697,48.226 U3.A24@45.724,48.254
NetR65_2: R65.2 U29.11 | length 2.2
  Top Layer w0.381: U29.11@33.619,58.949 33.629,58.939 35.803,58.939 R65.2@35.814,58.928
NetR66_1: R66.1 U3.A23 | length 21.9
  Top Layer w0.381: R66.1@37.366,60.198 40.369,60.198 cw(c40.369,59.64) 40.928,59.64 ; 40.933,59.64 40.933,50.237 ccw(c41.655,50.237) 41.655,49.515 ; 41.655,49.506 46.713,49.506 46.715,49.506 cw(c46.714,48.507) 47.422,49.212 U3.A23@48.573,48.061
NetR66_2: R66.2 U29.13 | length 2.6
  Top Layer w0.381: U29.13@33.619,61.489 34.543,61.489 cw(c34.543,60.899) 34.96,61.316 ; 34.955,61.311 R66.2@35.814,60.452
